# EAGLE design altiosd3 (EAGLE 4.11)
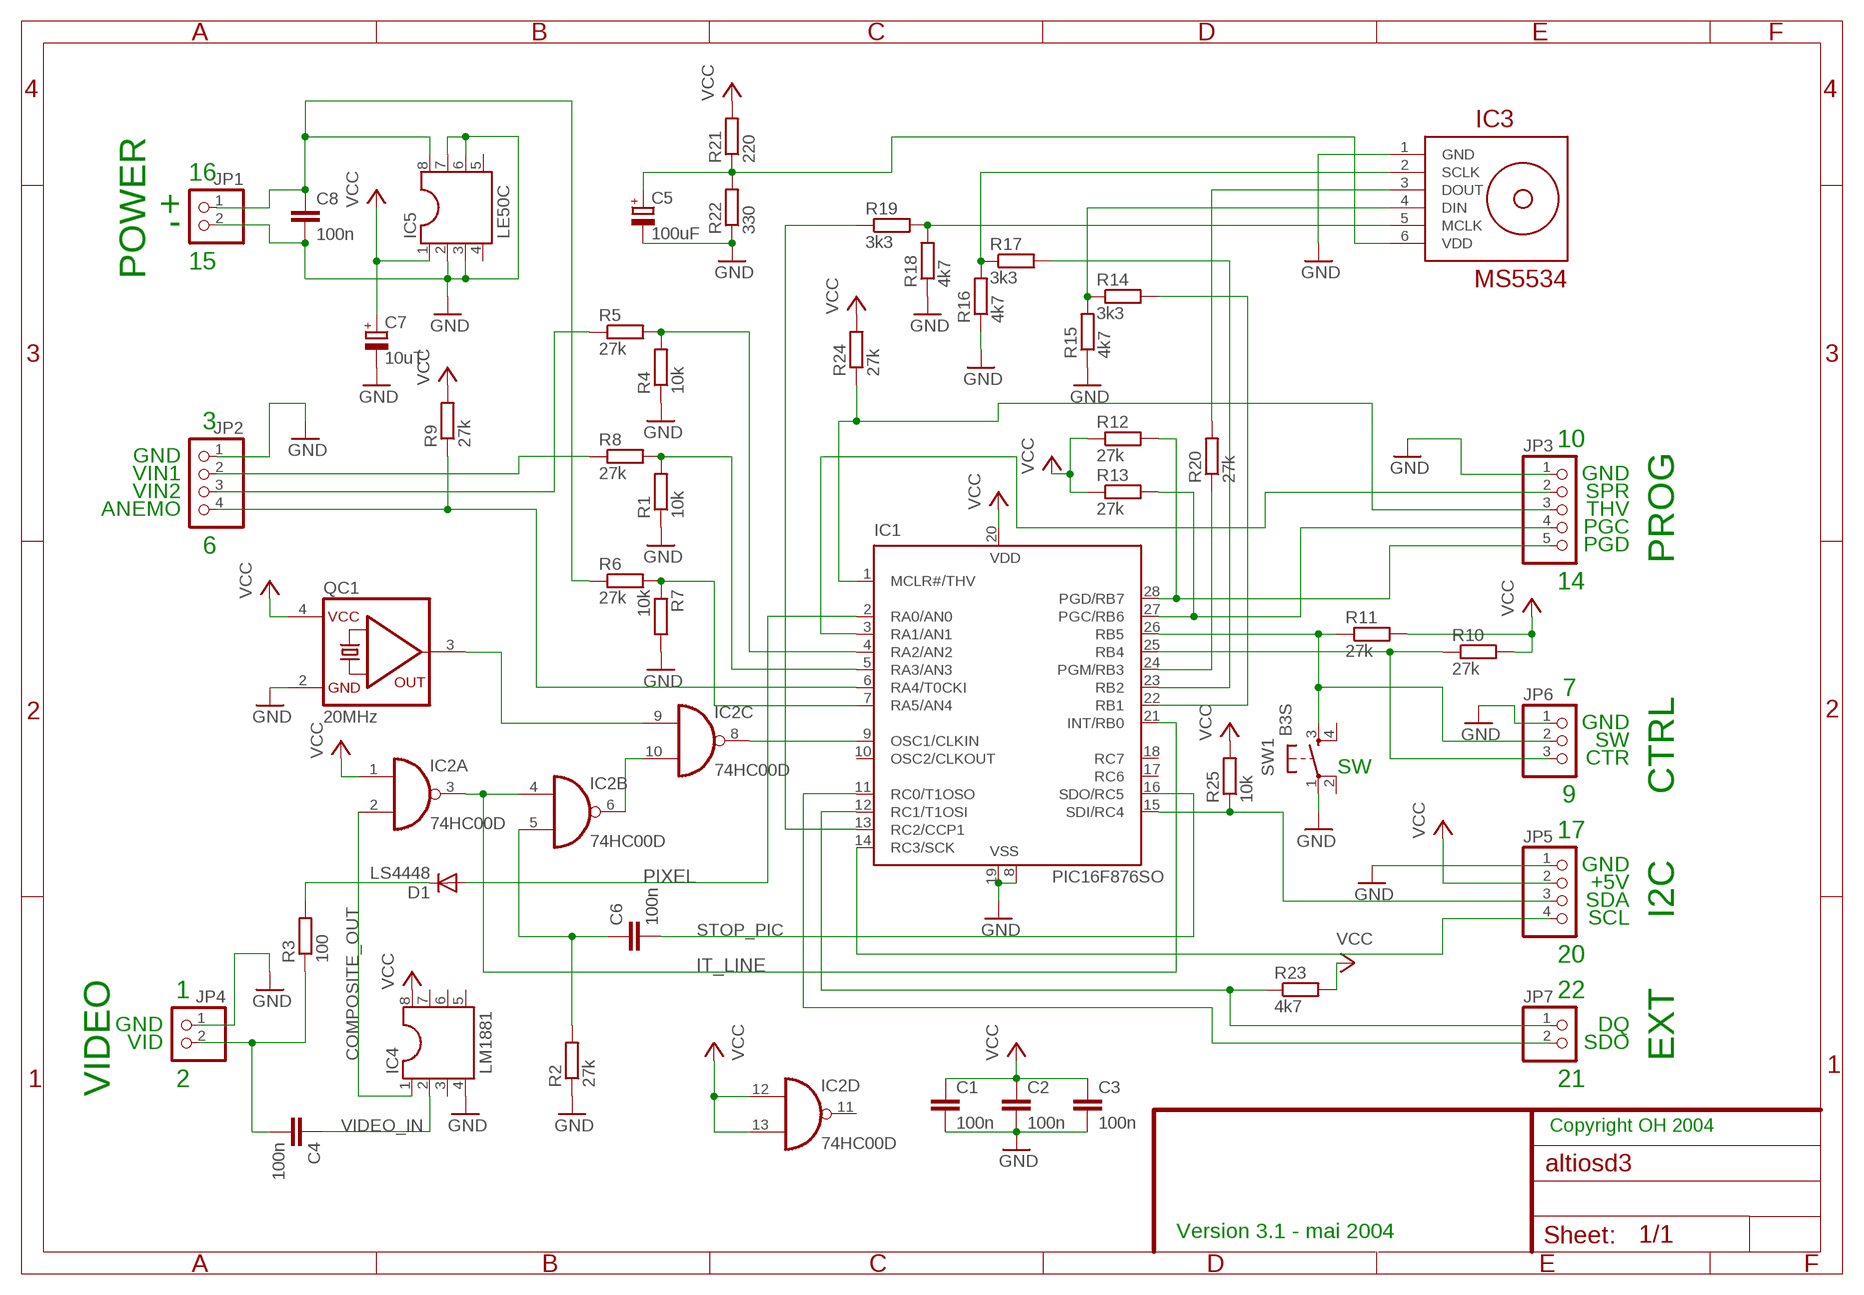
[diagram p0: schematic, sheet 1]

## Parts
C1  100n  C-EUC0805  [C0805]
C2  100n  C-EUC0805  [C0805]
C3  100n  C-EUC0805  [C0805]
C4  100n  C-EUC0805  [C0805]
C5  100uF  CPOL-EUD/7343-31R  [D/7343-31R]
C6  100n  C-EUC0805  [C0805]
C7  10uT  CPOL-EUCT3528  [CT3528]
C8  100n  C-EUC0805  [C0805]
D1  LS4448  DIODE-SOD80C  [SOD80C]
IC1  PIC16F876SO  [SO-28W]
IC2  74HC00D  [SO14]
IC3  MS5534  [MS5534]
IC4  LM1881  DIL8SO  [SO08]
IC5  LE50C  DIL8SO  [SO08]
JP1  PINHD-1X2  [1X02]
JP2  PINHD-1X4  [1X04]
JP3  PINHD-1X5  [1X05]
JP4  PINHD-1X2  [1X02]
JP5  PINHD-1X4  [1X04]
JP6  PINHD-1X3  [1X03]
JP7  PINHD-1X2  [1X02]
QC1  20MHz  OSC_OH  [OSC5X7]
R1  10k  R-EU_R0805  [R0805]
R2  27k  R-EU_R0805  [R0805]
R3  100  R-EU_R0805  [R0805]
R4  10k  R-EU_R0805  [R0805]
R5  27k  R-EU_R0805  [R0805]
R6  27k  R-EU_R0805  [R0805]
R7  10k  R-EU_R0805  [R0805]
R8  27k  R-EU_R0805  [R0805]
R9  27k  R-EU_R0805  [R0805]
R10  27k  R-EU_R0805  [R0805]
R11  27k  R-EU_R0805  [R0805]
R12  27k  R-EU_R0805  [R0805]
R13  27k  R-EU_R0805  [R0805]
R14  3k3  R-EU_R0805  [R0805]
R15  4k7  R-EU_R0805  [R0805]
R16  4k7  R-EU_R0805  [R0805]
R17  3k3  R-EU_R0805  [R0805]
R18  4k7  R-EU_R0805  [R0805]
R19  3k3  R-EU_R0805  [R0805]
R20  27k  R-EU_R0805  [R0805]
R21  220  R-EU_R0805  [R0805]
R22  330  R-EU_R0805  [R0805]
R23  4k7  R-EU_R0805  [R0805]
R24  27k  R-EU_R0805  [R0805]
R25  10k  R-EU_R0805  [R0805]
SW1  B3S  [B3S/CMS]

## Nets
ANEMO: IC1.6(RA4/T0CKI) JP2.4 R9.1
COMPOSITE_OUT: IC2.2(A:I1) IC4.1
CTR: IC1.25(RB4) JP6.3 R10.1
DQ: IC1.12(RC1/T1OSI) JP7.1 R23.1
GND: C1.2 C2.2 C3.2 C5.- C7.- C8.2 IC1.8(VSS) IC1.19(VSS) IC3.1(GND) IC4.4 IC5.2 IC5.3 IC5.6 IC5.7 JP1.2 JP2.1 JP3.1 JP4.1 JP5.1 JP6.1 QC1.2(GND) R1.1 R2.1 R4.1 R7.2 R15.1 R16.1 R18.1 R22.1 SW1.1(P)
IT_LINE: IC1.21(INT/RB0) IC2.3(A:O) IC2.4(B:I0)
N$1: IC2.9(C:I0) QC1.3(OUT)
N$2: IC1.9(OSC1/CLKIN) IC2.8(C:O)
N$3: IC2.6(B:O) IC2.10(C:I1)
N$7: IC1.5(RA3/AN3) R1.2 R8.2
N$11: IC1.4(RA2/AN2) R4.2 R5.2
N$15: IC3.3(DOUT) R20.2
N$16: C6.1 IC2.5(B:I1) R2.2
N$18: D1.C R3.2
N$21: IC1.7(RA5/AN4) R6.2 R7.1
N$23: IC3.5(MCLK) R18.2 R19.2
N$25: IC1.13(RC2/CCP1) R19.1
N$27: IC1.22(RB1) R14.2
N$30: IC1.24(PGM/RB3) R20.1
N$31: IC1.23(RB2) R17.2
N$32: C5.+ IC3.6(VDD) R21.1 R22.2
N$33: IC3.4(DIN) R14.1 R15.2
N$35: IC3.2(SCLK) R16.2 R17.1
PGC: IC1.27(PGC/RB6) JP3.4 R13.2
PGD: IC1.28(PGD/RB7) JP3.5 R12.2
PIXEL: D1.A IC1.2(RA0/AN0)
SCL: IC1.14(RC3/SCK) JP5.4
SDA: IC1.15(SDI/RC4) JP5.3 R25.1
SDO: IC1.11(RC0/T1OSO) JP7.2
SPR: IC1.3(RA1/AN1) JP3.2
STOP_PIC: C6.2 IC1.16(SDO/RC5)
SW: IC1.26(RB5) JP6.2 R11.1 SW1.3(S)
THV: IC1.1(MCLR#/THV) JP3.3 R24.1
V+: C8.1 IC5.8 JP1.1 R6.1
VCC: C1.1 C2.1 C3.1 C7.+ IC1.20(VDD) IC2.1(A:I0) IC2.12(D:I0) IC2.13(D:I1) IC4.8 IC5.1 JP5.2 QC1.4(VCC) R9.2 R10.2 R11.2 R12.1 R13.1 R21.2 R23.2 R24.2 R25.2
VID: C4.2 JP4.2 R3.1
VIDEO_IN: C4.1 IC4.2
VIN1: JP2.2 R8.1
VIN2: JP2.3 R5.1
Unconnected: IC1.10(OSC2/CLKOUT) IC1.17(RC6) IC1.18(RC7) IC2.11(D:O) IC4.3 IC4.5 IC4.6 IC4.7 IC5.4 IC5.5 SW1.2(P1) SW1.4(S1)

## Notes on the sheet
- 16
- +
- -
- 15
- POWER
- 3
- 10
- GND
- VIN1 | GND
- VIN2 | SPR
- ANEMO | THV
- PGC
- 6 | PGD
- PROG
- 14
- 7
- GND
- SW
- CTR
- SW
- 9
- CTRL
- 17
- GND
- +5V
- SDA
- SCL
- I2C
- 20
- 1 | 22
- GND | DQ
- VID | SDO
- EXT
- 2 | 21
- VIDEO
- Copyright OH 2004
- Version 3.1 - mai 2004

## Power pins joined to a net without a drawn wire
GND: IC2.7(GND)
VCC: IC2.14(VCC)

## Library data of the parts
C1-C4 C6 C8 = rcl:C-EU: CAPACITOR, European symbol
C5 C7 = rcl:CPOL-EU: POLARIZED CAPACITOR, European symbol
D1 = diode:DIODE-: DIODE
IC1 = microchip:PIC16*876: MICROCONTROLLER flash type
IC2 = 74xx-eu_1:74*00: Quad 2-input NAND gate
IC3 = _ohlib:MS5534: Intersema Barometer Module
IC4 IC5 = dil:DIL8: SOCKET Dual In Line
JP1 JP4 JP7 = pinhead:PINHD-1X2: PIN HEADER
JP2 JP5 = pinhead:PINHD-1X4: PIN HEADER
JP3 = pinhead:PINHD-1X5: PIN HEADER
JP6 = pinhead:PINHD-1X3: PIN HEADER
QC1 = crystal:OSC_OH
R1-R25 = rcl:R-EU_: RESISTOR, European symbol
SW1 = switch-omron:B3S: OMRON B3S (CMS)

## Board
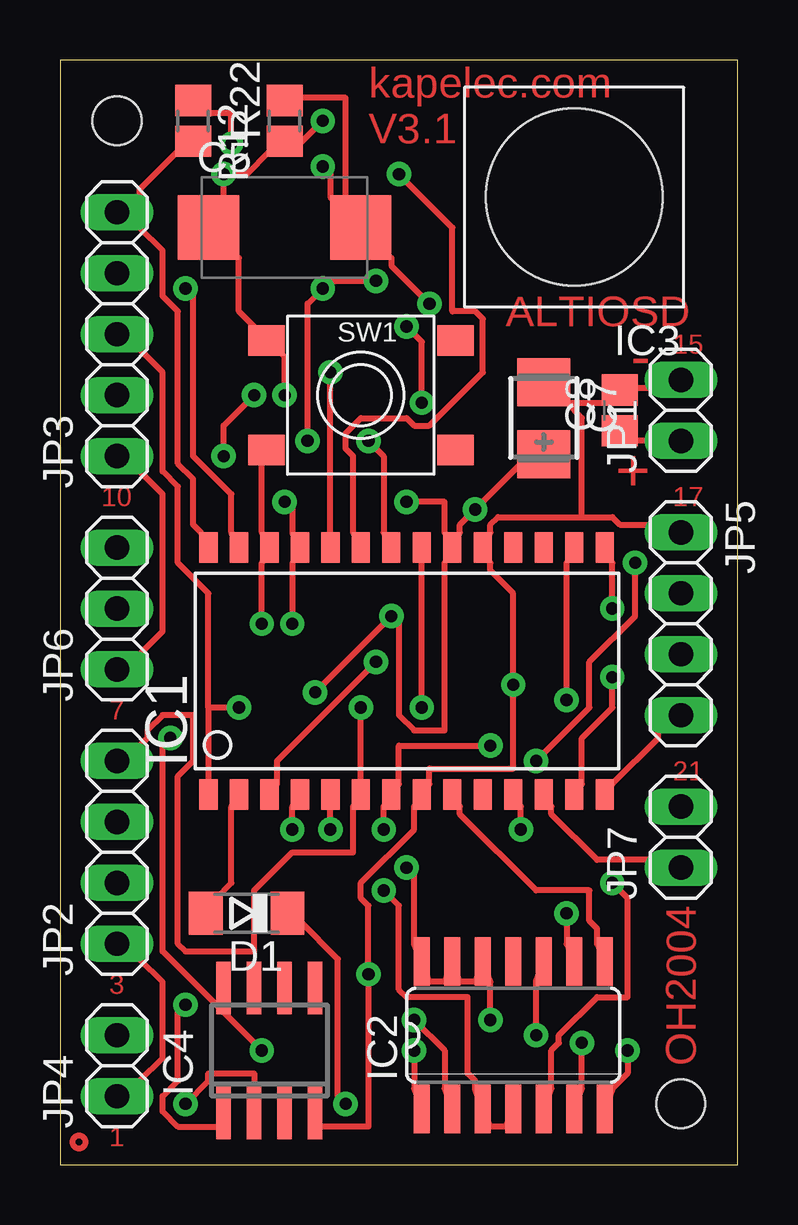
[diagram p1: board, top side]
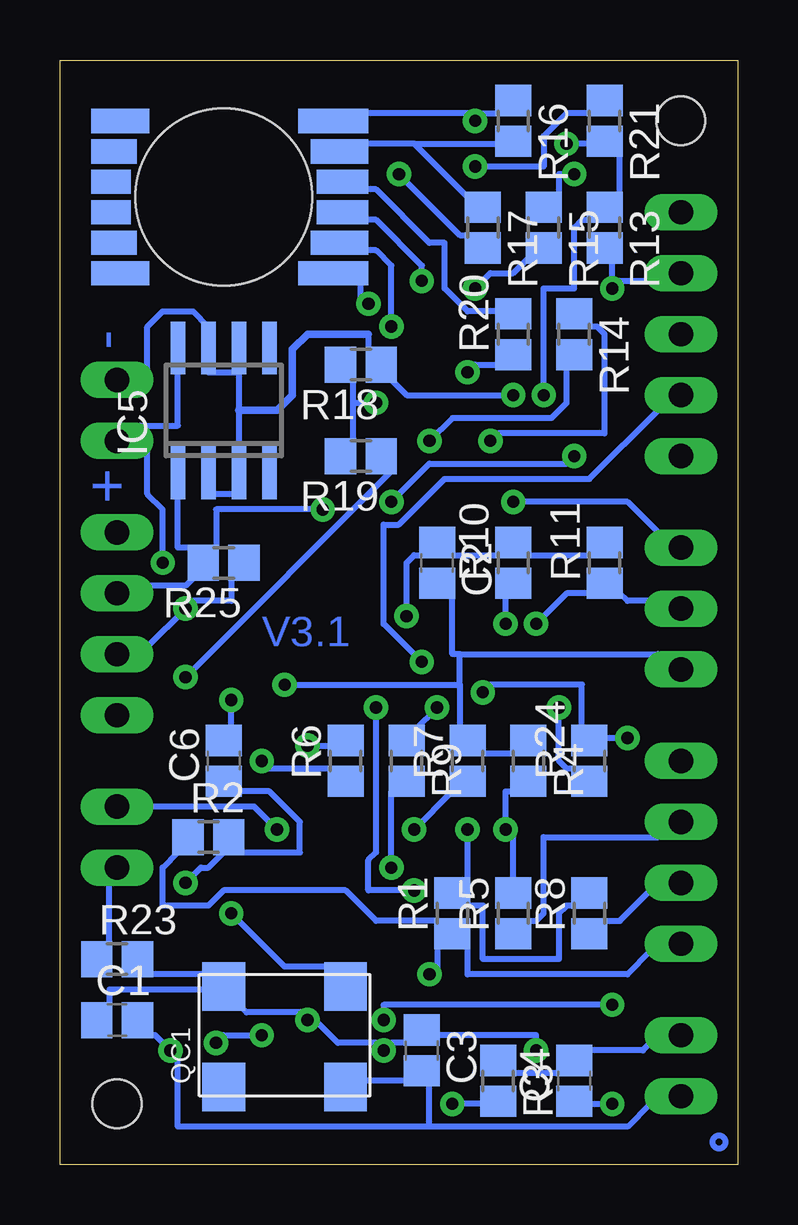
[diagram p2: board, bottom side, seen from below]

Size 28.25 x 46.03 mm. Coordinates in mm from the lower left corner, seen from the top.
Outline: 0,0 28.25,0 28.25,46.03 0,46.03 0,0
Copper layers (1*16): Top 0.035mm / dielectric 1.5mm / Bottom 0.035mm
Design rules "default": minimum track width 10mil, minimum drill 20mil, track to track 10mil, track to pad 10mil, pad to pad 10mil, via to via 10mil, smd to smd 10mil, copper to edge 40mil, drill to drill 8mil, minimum pad ring 8mil, minimum via ring 10mil, stop-mask expansion 4mil, vias tented up to drill 0mil, thermal gap 10mil
Holes 2.03 mm at 2.38,43.49 25.87,2.54

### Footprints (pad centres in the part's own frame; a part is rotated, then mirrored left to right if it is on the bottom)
C0805 = smd 1.3 x 1.5: 1 -0.85,0; 2 0.85,0
D/7343-31R = smd 2.55 x 2.7: + 3.175,0; - -3.175,0
CT3528 = smd 2 x 2.2: + 1.5,0; - -1.5,0
SOD80C = smd 1.4 x 1.8: A 1.7,0; C -1.7,0
SO-28W = smd 0.762 x 1.27: 1 -7.62,-5.207; 2 -6.35,-5.207; 3 -5.08,-5.207; 4 -3.81,-5.207; 5 -2.54,-5.207; 6 -1.27,-5.207; 7 0,-5.207; 8 1.27,-5.207; 9 2.54,-5.207; 10 3.81,-5.207; 11 5.08,-5.207; 12 6.35,-5.207; 13 7.62,-5.207; 14 8.89,-5.207; 15 8.89,5.08; 16 7.62,5.08; 17 6.35,5.08; 18 5.08,5.08; 19 3.81,5.08; 20 2.54,5.08; 21 1.27,5.08; 22 0,5.08; 23 -1.27,5.08; 24 -2.54,5.08; 25 -3.81,5.08; 26 -5.08,5.08; 27 -6.35,5.08; 28 -7.62,5.08
SO14 = smd 0.66 x 2.032: 1 -3.81,-3.073; 2 -2.54,-3.073; 3 -1.27,-3.073; 4 0,-3.073; 5 1.27,-3.073; 6 2.54,-3.073; 7 3.81,-3.073; 8 3.81,3.073; 9 2.54,3.073; 10 1.27,3.073; 11 0,3.073; 12 -1.27,3.073; 13 -2.54,3.073; 14 -3.81,3.073
MS5534 = smd 2.921 x 1.016 bottom: 1 4.572,-2.54; 6 4.572,3.81 | smd 2.413 x 1.016 bottom: 2 4.826,-1.27; 5 4.826,2.54; 7 -4.318,3.81; 12 -4.318,-2.54 | smd 2.159 x 1.016 bottom: 3 4.953,0; 4 4.953,1.27 | smd 1.905 x 1.016 bottom: 8 -4.572,2.54; 11 -4.572,-1.27 | smd 1.651 x 1.016 bottom: 9 -4.699,1.27; 10 -4.699,0 | hole 7.366: 0,0.635
SO08 = smd 0.6 x 2.2: 1 -1.905,-2.6; 2 -0.635,-2.6; 3 0.635,-2.6; 4 1.905,-2.6; 5 1.905,2.6; 6 0.635,2.6; 7 -0.635,2.6; 8 -1.905,2.6
1X02 = drill 1.016 long: 1 -1.27,0; 2 1.27,0
1X04 = drill 1.016 long: 1 -3.81,0; 2 -1.27,0; 3 1.27,0; 4 3.81,0
1X05 = drill 1.016 long: 1 -5.08,0; 2 -2.54,0; 3 0,0; 4 2.54,0; 5 5.08,0
1X03 = drill 1.016 long: 1 -2.54,0; 2 0,0; 3 2.54,0
OSC5X7 = smd 1.778 x 2.032: 1 -2.54,-2.159; 2 2.54,-2.159; 3 2.54,2.032; 4 -2.54,2.032
R0805 = smd 1.3 x 1.5: 1 -0.85,0; 2 0.85,0
B3S/CMS = smd 1.524 x 1.27: 1 3.937,-2.286; 2 -3.937,-2.286; 3 3.937,2.286; 4 -3.937,2.286

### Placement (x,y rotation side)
C1  25.87,6.03 0 bottom
C2  12.54,25.08 270 bottom
C3  13.17,4.76 270 bottom
C4  6.82,3.49 90 bottom
C5  9.36,39.05 0 top
C6  21.43,16.82 90 bottom
C7  20.16,31.11 270 top
C8  23.33,31.43 90 top
D1  7.77,10.47 180 top
IC1  13.81,20.63 0 top
IC2  18.89,5.39 0 top
IC3  21.43,40.95 180 top
IC4  8.73,4.76 0 top
IC5  21.43,31.43 0 bottom
JP1  25.87,31.43 90 top
JP2  2.38,13.01 90 top
JP3  2.38,34.6 90 top
JP4  2.38,4.12 90 top
JP5  25.87,22.54 270 top
JP6  2.38,23.17 90 top
JP7  25.87,13.65 90 top
QC1  18.89,5.39 0 bottom
R1  11.9,10.47 90 bottom
R2  22.06,13.65 0 bottom
R3  10,3.49 270 bottom
R4  8.73,16.82 270 bottom
R5  9.36,10.47 90 bottom
R6  16.35,16.82 90 bottom
R7  11.27,16.82 90 bottom
R8  6.18,10.47 90 bottom
R9  13.81,16.82 270 bottom
R10  9.36,25.08 90 bottom
R11  5.55,25.08 90 bottom
R12  5.55,43.49 270 top
R13  5.55,39.05 270 bottom
R14  6.82,34.6 270 bottom
R15  8.09,39.05 270 bottom
R16  9.36,43.49 270 bottom
R17  10.63,39.05 270 bottom
R18  15.71,33.33 180 bottom
R19  15.71,29.52 180 bottom
R20  9.36,34.6 90 bottom
R21  5.55,43.49 270 bottom
R22  9.36,43.49 90 top
R23  25.87,8.57 0 bottom
R24  6.18,16.82 90 bottom
R25  21.43,25.08 180 bottom
SW1  12.54,32.06 180 top

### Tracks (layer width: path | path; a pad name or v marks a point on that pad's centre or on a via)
ANEMO  (via drill 0.51)
  Top 0.254: v12.54,19.05 IC1.6 12.22,14.92 12.22,13.01 9.68,13.01 8.09,11.42 8.09,8.88 5.23,8.88 4.92,9.2 4.92,16.19 5.55,16.82 5.55,18.73 4.28,18.73 3.65,18.09 3.65,17.78 3.33,17.46 JP2.4
  Bottom 0.254: v12.54,19.05 13.49,18.09 R9.1
COMPOSITE_OUT  (via drill 0.51)
  Top 0.254: v14.76,6.03 16.03,4.76 16.03,3.17 IC2.2 | v5.23,6.66 4.92,6.34 4.92,3.49 4.28,2.85 4.28,2.22 4.92,1.58 6.82,1.58 IC4.1
  Bottom 0.254: v14.76,6.03 14.76,6.66 v5.23,6.66
CTR  (via drill 0.51)
  Top 0.254: v9.68,22.54 9.68,25.08 IC1.25 9.68,26.35 9.68,27.3 v9.36,27.62
  Bottom 0.254: v9.68,22.54 9.68,23.81 R10.1 | v9.36,27.62 4.6,27.62 3.33,26.35 JP6.3
DQ
  Top 0.254: IC1.12 20.47,14.92 20.47,14.6 22.38,12.69 24.6,12.69 JP7.1
  Bottom 0.254: R23.1 26.19,9.2 26.19,11.74 JP7.1
GND  (via drill 0.51)
  Top 0.254: v23.65,4.76 23.65,3.81 23.01,3.17 IC2.7 | JP4.1 3.33,3.49 4.28,4.44 4.28,7.62 3.33,8.57 JP2.1 | JP3.1 3.33,28.89 4.28,27.94 4.28,22.22 3.33,21.27 JP6.1 | v10.95,43.49 10,42.54 R22.1 8.73,42.22 7.77,41.27 v6.82,41.27 6.82,40.32 C5.- 7.46,37.78 7.46,35.55 8.09,34.92 SW1.1 9.04,33.97 9.36,33.65 v9.36,32.06 | JP1.2 24.6,32.38 23.96,32.38 C8.2 22.7,31.75 21.11,31.75 | 21.11,31.75 21.74,31.11 21.74,26.98 | 21.11,31.75 C7.- | IC4.4 10.63,1.58 12.85,1.58 v12.85,7.93 12.85,10.79 12.54,11.11 12.54,11.74 14.76,13.96 14.76,14.92 IC1.8 15.39,15.87 15.39,16.51 18.89,16.51 v18.89,20 18.89,23.81 17.93,24.76 17.93,25.08 IC1.19 17.93,26.35 17.93,26.67 18.25,26.98 21.74,26.98 | JP5.1 24.6,26.67 23.33,26.67 23.01,26.98 21.74,26.98
  Bottom 0.254: C1.2 24.6,5.39 24.28,5.39 v23.65,4.76 23.33,4.44 23.33,1.58 12.85,1.58 | QC1.2 15.71,3.49 13.81,3.49 C3.2 12.85,3.49 12.85,1.58 | R1.1 11.27,9.2 11.27,7.93 4.6,7.93 3.65,8.88 JP2.1 | R2.1 23.33,13.01 23.96,12.38 23.96,10.79 22.06,10.79 21.43,11.42 16.35,11.42 15.08,10.15 12.54,10.15 R1.1 | 12.85,1.58 4.6,1.58 3.65,2.54 JP4.1 | R4.1 9.36,17.14 10.63,17.14 R7.2 11.58,18.09 11.58,20 | 11.58,21.27 3.33,21.27 JP6.1 | 11.58,21.27 11.9,21.27 11.9,23.81 C2.2 | 11.58,20 11.58,21.27 | 10.95,43.81 15.71,43.81 IC3.1 | 10.95,43.81 10,43.81 R16.1 | v6.82,41.27 7.46,41.27 7.46,40.32 R15.1 | v10.95,43.49 10.95,43.81 | IC5.2 22.06,27.94 20.79,27.94 IC5.3 20.79,31.43 20.79,33.02 | 15.39,34.6 15.39,33.97 R18.1 14.44,32.7 13.81,32.06 v9.36,32.06 | 20.79,33.02 22.06,33.02 IC5.7 22.06,34.92 22.7,35.55 23.96,35.55 24.6,34.92 24.6,32.7 JP1.2 | 20.79,33.02 IC5.6 | v18.89,20 11.58,20 | v12.85,7.93 12.54,7.93 12.54,9.2 R1.1
  Bottom 0.305: 15.39,34.6 17.93,34.6 18.57,33.97 18.57,32.06 19.2,31.43 20.79,31.43
IT_LINE  (via drill 0.51)
  Top 0.254: v13.49,11.42 14.12,10.79 14.12,7.3 14.44,6.98 16.98,6.98 16.98,3.81 17.3,3.49 17.3,3.17 IC2.3 17.93,1.58 18.57,1.58 IC2.4 | v15.08,19.05 IC1.21
  Bottom 0.254: v15.08,19.05 15.08,13.01 15.39,12.69 15.39,11.42 v13.49,11.42
N$1  (via drill 0.51)
  Top 0.254: v21.11,10.47 21.11,9.2 IC2.9
  Bottom 0.254: v21.11,10.47 18.89,8.25 16.98,8.25 QC1.3
N$2
  Top 0.254: IC1.9 16.66,14.92 16.66,14.6 19.84,11.42 22.06,11.42 22.06,10.15 22.38,9.84 22.38,9.2 IC2.8
N$3  (via drill 0.51)
  Top 0.254: v21.74,5.08 21.74,3.17 IC2.6 | v19.84,5.39 19.84,7.62 IC2.10
  Bottom 0.254: v21.74,5.08 21.43,5.39 v19.84,5.39
N$7  (via drill 0.51)
  Top 0.254: v11.27,13.96 IC1.5
  Bottom 0.254: v11.27,13.96 11.27,11.74 R1.2 11.27,10.79 10.63,10.79 10.63,8.57 7.46,8.57 7.46,10.47 7.14,10.79 6.82,10.79 R8.2
N$11  (via drill 0.51)
  Top 0.254: v9.68,13.96 9.68,14.92 IC1.4
  Bottom 0.254: R4.2 9.36,15.55 9.68,15.55 v9.68,13.96 9.36,13.65 R5.2
N$15
  Bottom 0.254: R20.2 10,35.55 11.27,35.55 12.22,36.51 12.22,38.41 12.85,38.41 15.08,40.63 15.71,40.63 IC3.3
N$16  (via drill 0.51)
  Top 0.254: v23.01,11.74 23.65,11.11 23.65,6.98 22.38,6.98 20.79,5.39 20.79,5.08 20.47,4.76 20.47,3.17 IC2.5
  Bottom 0.254: v23.01,11.74 22.38,12.38 22.06,12.38 21.43,13.01 R2.2 20.79,13.01 18.25,13.01 18.25,14.28 19.52,15.55 20.79,15.55 C6.1
N$18  (via drill 0.51)
  Top 0.254: v11.9,2.54 11.58,2.85 11.58,8.57 10,10.15 D1.C
  Bottom 0.254: v11.9,2.54 10.63,2.54 R3.2
N$21  (via drill 0.51)
  Top 0.254: v13.49,13.96 13.49,14.92 IC1.7 14.12,15.87 14.12,17.46 v17.93,17.46
  Bottom 0.254: v13.49,13.96 11.9,15.55 R7.1 | v17.93,17.46 16.98,17.46 R6.2
N$23  (via drill 0.51)
  Top 0.254: v14.44,34.92 15.08,34.28 v15.08,31.75
  Bottom 0.254: 16.03,31.75 16.03,32.7 R18.2 | 16.03,31.75 16.03,30.16 R19.2 | v14.44,34.92 14.44,37.46 15.08,38.09 15.71,38.09 IC3.5 | 16.03,31.75 v15.08,31.75
N$25  (via drill 0.51)
  Top 0.254: v23.01,20.32 23.01,19.05 21.74,17.78 21.74,15.87 IC1.13
  Bottom 0.254: v23.01,20.32 14.44,28.89 R19.1
N$27  (via drill 0.51)
  Top 0.254: v12.85,30.16 13.49,29.52 13.49,26.35 IC1.22
  Bottom 0.254: v12.85,30.16 11.9,31.11 7.77,31.11 7.14,31.75 7.14,33.33 R14.2
N$30  (via drill 0.51)
  Top 0.254: IC1.24 v11.27,33.02
  Bottom 0.254: v11.27,33.02 10.95,33.33 10,33.33 R20.1
N$31  (via drill 0.51)
  Top 0.254: v14.12,41.27 16.35,39.05 16.35,35.55 17.3,35.55 17.62,35.24 17.62,33.02 15.39,30.79 14.76,30.79 14.44,31.11 12.54,31.11 11.9,30.48 11.9,29.84 12.22,29.52 12.22,26.35 IC1.23
  Bottom 0.254: v14.12,41.27 11.58,38.73 11.27,38.73 R17.2
N$32  (via drill 0.51)
  Top 0.254: v10.95,41.59 11.27,41.27 11.27,40.32 C5.+ | R22.2 10,44.45 11.9,44.45 11.9,40.32 C5.+ | v15.39,35.87 13.81,37.46 13.81,37.78 C5.+
  Bottom 0.254: v10.95,41.59 8.09,41.59 8.09,42.86 7.14,43.81 6.18,43.81 R21.1 | v15.39,35.87 15.71,35.87 15.71,36.82 IC3.6
N$33  (via drill 0.51)
  Top 0.254: v10.31,30.16 10.31,35.87 v10.95,36.51 11.27,36.82 v13.17,36.82
  Bottom 0.254: v10.31,30.16 10,30.48 5.55,30.48 5.55,34.6 5.87,34.92 6.18,34.92 R14.1 | v10.95,36.51 10.31,37.14 9.36,37.14 8.73,37.78 R15.2 | v13.17,36.82 13.17,37.46 15.08,39.36 15.71,39.36 IC3.4
N$35
  Bottom 0.254: 13.49,42.54 15.71,42.54 IC3.2 | 13.49,42.54 10,42.54 R16.2 | 13.49,42.54 11.27,40.32 R17.1
PGC  (via drill 0.51)
  Top 0.254: v5.23,36.51 5.55,36.19 5.55,29.52 7.14,27.94 7.14,26.35 IC1.27
  Bottom 0.254: R13.2 5.23,37.78 v5.23,36.51 4.92,36.82 3.65,36.82 JP3.4
PGD
  Top 0.254: IC1.28 5.87,26.35 5.55,26.67 5.55,28.57 4.92,29.21 4.92,35.55 4.28,36.19 4.28,38.09 3.33,39.05 JP3.5 3.33,40.32 3.33,40.63 4.92,42.22 R12.2
PIXEL
  Top 0.254: IC1.2 7.14,14.92 7.14,11.74 6.5,11.11 D1.A
SCL
  Top 0.254: IC1.14 23.01,15.87 24.92,17.78 24.92,18.09 JP5.4
SDA  (via drill 0.51)
  Top 0.254: v23.01,23.17 23.01,25.08 IC1.15
  Bottom 0.254: JP5.3 24.6,21.59 v23.01,23.17 22.7,23.49 21.11,23.49 21.11,24.44 R25.1
SDO  (via drill 0.51)
  Top 0.254: v19.2,13.96 19.2,14.92 IC1.11
  Bottom 0.254: v19.2,13.96 20.16,14.92 JP7.2
SPR  (via drill 0.51)
  Top 0.254: v13.17,20.95 9.04,16.82 9.04,15.87 IC1.3
  Bottom 0.254: v13.17,20.95 14.76,22.54 14.76,26.67 14.12,26.67 12.22,28.57 6.18,28.57 3.33,31.43 JP3.2
STOP_PIC  (via drill 0.51)
  Top 0.254: v21.11,19.36 21.11,25.08 IC1.16
  Bottom 0.254: v21.11,19.36 21.11,18.09 C6.2
SW  (via drill 0.51)
  Top 0.254: SW1.3 8.41,29.21 8.41,26.35 IC1.26 8.41,25.08 v8.41,22.54
  Bottom 0.254: JP6.2 3.65,23.49 4.6,23.49 4.92,23.81 R11.1 6.18,23.81 7.14,23.81 v8.41,22.54
THV  (via drill 0.51)
  Top 0.254: 6.18,19.05 6.18,23.81 4.92,25.08 4.92,28.25 4.28,28.89 4.28,33.02 3.33,33.97 JP3.3 | 6.18,19.05 IC1.1 | v7.46,19.05 6.18,19.05
  Bottom 0.254: v7.46,19.05 7.46,16.82 7.14,16.51 6.82,16.51 R24.1
V+  (via drill 0.51)
  Top 0.254: v19.84,16.82 22.06,19.05 22.06,20.95 23.96,22.86 v23.96,25.08 | C8.1 23.96,30.16 JP1.1
  Bottom 0.254: v19.84,16.82 19.52,16.51 16.98,16.51 R6.1 | v23.96,25.08 23.96,27.3 24.6,27.94 24.6,30.16 JP1.1 24.92,30.79 23.33,30.79 IC5.8
VCC  (via drill 0.51)
  Top 0.254: v14.44,12.38 14.76,12.06 14.76,9.2 IC2.14 15.39,7.62 16.03,7.62 IC2.13 16.66,7.62 17.3,7.62 IC2.12 17.93,7.62 v17.93,6.03 | v14.76,4.76 14.76,3.17 IC2.1 | 6.82,6.34 v8.41,4.76 | v4.6,17.78 4.28,17.46 4.28,8.88 6.82,6.34 | IC4.8 6.82,6.34 | v7.14,42.54 7.14,43.81 6.18,43.81 R12.1 | IC1.20 16.66,26.35 16.66,26.67 v17.3,27.3 19.2,29.21 C7.+ | v8.09,32.06 6.82,30.79 v6.82,29.52 | v14.44,27.62 16.03,27.62 16.03,26.35 IC1.20 | IC1.20 16.03,25.08 16.03,18.09 14.76,18.09 14.12,18.73 14.12,22.54 v13.81,22.86 v10.63,19.68
  Bottom 0.254: v14.44,12.38 14.44,15.55 R9.2 | R23.2 24.6,7.93 22.06,7.93 QC1.4 | C1.1 26.19,6.66 26.19,7.3 22.06,7.3 QC1.4 | v8.41,4.76 8.41,5.39 12.54,5.39 C3.1 13.81,5.08 14.44,5.08 v14.76,4.76 15.08,5.08 16.66,5.08 17.62,6.03 | v4.6,17.78 5.55,17.78 R24.2 6.5,18.09 6.5,20 10.31,20 v10.63,19.68 | 17.62,6.03 17.93,6.34 20.47,6.34 20.79,6.66 QC1.4 | 17.62,6.03 v17.93,6.03 | R25.2 22.7,24.44 23.01,24.12 24.6,24.12 JP5.2 | IC5.1 23.33,25.71 22.7,25.71 R25.2 | R11.2 6.18,25.39 8.73,25.39 R10.2 10,25.39 11.9,25.39 C2.1 13.17,25.39 13.49,25.39 13.81,25.08 v13.81,22.86 | v7.14,42.54 6.18,42.54 R21.2 4.92,42.22 4.92,40.32 R13.1 6.18,39.36 6.5,39.36 6.82,39.05 6.82,36.51 8.09,36.51 v8.09,32.06 | v6.82,29.52 7.14,29.21 12.85,29.21 v14.44,27.62 | v17.3,27.3 21.74,27.3 21.74,25.71 R25.2
VID
  Bottom 0.254: R3.1 9.36,3.81 7.46,3.81 C4.2 6.18,4.76 3.96,4.76 3.65,5.08 JP4.2
VIDEO_IN  (via drill 0.51)
  Top 0.254: v5.23,2.54 6.18,3.49 6.18,3.81 8.09,3.81 IC4.2
  Bottom 0.254: v5.23,2.54 6.18,2.54 C4.1
VIN1
  Bottom 0.254: R8.1 5.55,10.15 4.92,10.15 3.65,11.42 JP2.2
VIN2
  Bottom 0.254: R5.1 8.73,10.15 8.41,10.15 8.09,10.47 8.09,13.65 3.33,13.65 JP2.3
(copper drawn outside any net)
  shapes: Bottom circle x1, Top circle x1

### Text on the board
Top: kapelec.com | V3.1 | ALTIOSD | - | 15 | + | 10 | 17 | 7 | 21 | 3 | OH2004 | 1
Bottom: - | + | V3.1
